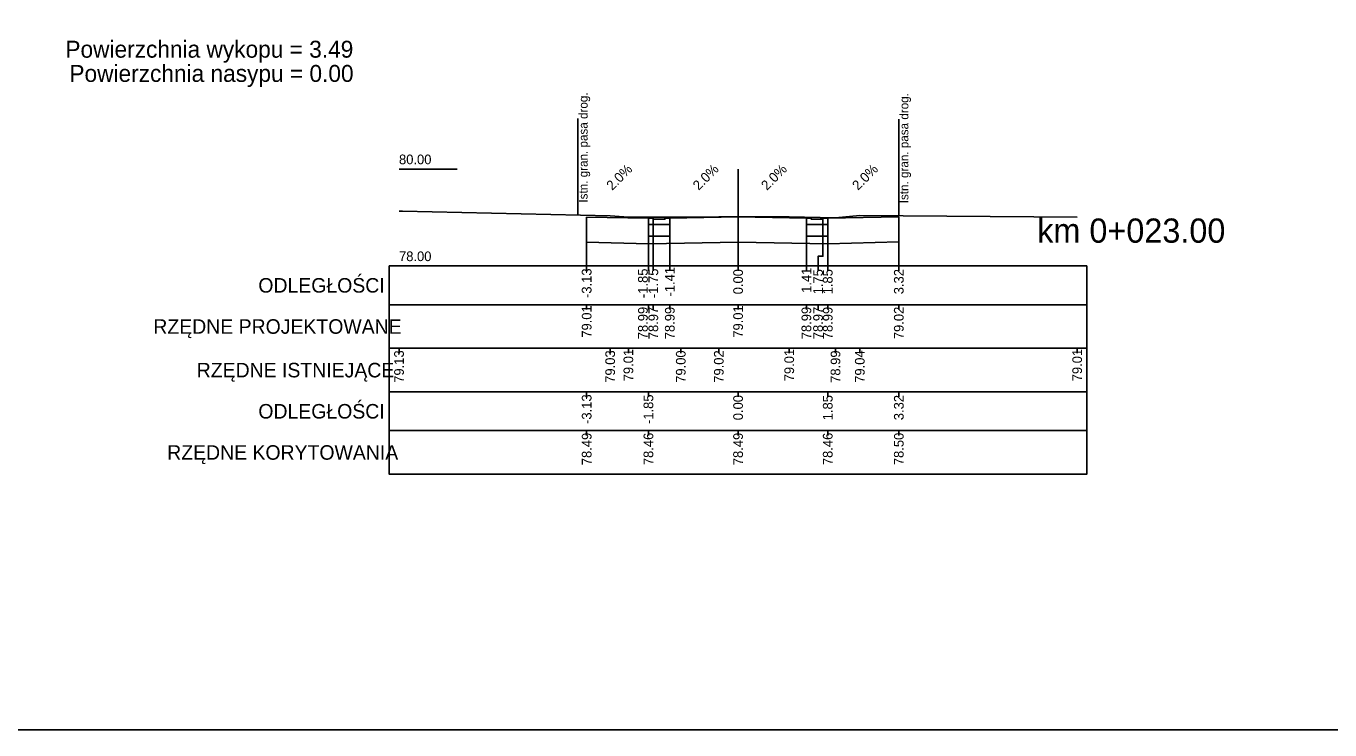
# Model space of a CAD drawing. Extents: x 7492871 to 7493499, y 5802964 to 5802992.
# Drawn here: x 7492987.07 to 7493013.99, y 5802963.88 to 5802978.41 of the extents above; entities that cross this region are included whole.
import ezdxf

# ---------------------------------------------------------------- set-up
doc = ezdxf.new("R2010")
doc.units = 0
for name, color, linetype in [('_wydruk', 7, 'Continuous'), ('d_pop_nasyp_opis', 7, 'Continuous'), ('d_pop_wykop_opis', 7, 'Continuous'), ('opisy_ramki_pop', 7, 'Continuous'), ('pop_comp_kostka', 7, 'Continuous'), ('pop_comp_lawa', 7, 'Continuous'), ('pop_comp_scieralna', 7, 'Continuous'), ('pop_granica_istn', 7, 'Continuous'), ('pop_opis', 7, 'Continuous'), ('pop_os', 7, 'Continuous'), ('pop_pikietaz', 7, 'Continuous'), ('pop_teren', 7, 'Continuous')]:
    doc.layers.add(name, color=color, linetype=linetype)

msp = doc.modelspace()

# ---------------------------------------------------------------- linework, layer by layer
msp.add_lwpolyline([(7492998.642, 5802974.47), (7492999.917, 5802974.445), (7493000.017, 5802974.445), (7493000.018, 5802974.425), (7493000.257, 5802974.425), (7493000.258, 5802974.445), (7493000.358, 5802974.445), (7493001.768, 5802974.473), (7493003.178, 5802974.445), (7493003.278, 5802974.445), (7493003.279, 5802974.425), (7493003.518, 5802974.425), (7493003.519, 5802974.445), (7493003.619, 5802974.445), (7493005.086, 5802974.474)])
at = {"layer": '_wydruk'}
msp.add_lwpolyline([(7492871.369, 5802992.281), (7493499.283, 5802992.281), (7493499.283, 5802963.881), (7492871.369, 5802963.881)], close=True, dxfattribs=at)
at = {"layer": 'opisy_ramki_pop'}
for points in [[(7492998.642, 5802973.95), (7492998.642, 5802973.659), (7492998.642, 5802973.659), (7492998.642, 5802973.459)], [(7492999.917, 5802973.916), (7492999.917, 5802973.659), (7492999.917, 5802973.659), (7492999.917, 5802973.459)], [(7493001.768, 5802973.953), (7493001.768, 5802973.659), (7493001.768, 5802973.659), (7493001.768, 5802973.459)], [(7493003.619, 5802973.916), (7493003.619, 5802973.659), (7493003.619, 5802973.659), (7493003.619, 5802973.459)], [(7493005.086, 5802973.954), (7493005.086, 5802973.659), (7493005.086, 5802973.659), (7493005.086, 5802973.459)]]:
    msp.add_lwpolyline(points, dxfattribs=at)
at = {"layer": 'pop_comp_kostka'}
for p, q in [((7493000.017, 5802974.445), (7492999.917, 5802974.445)), ((7492999.917, 5802974.445), (7492999.917, 5802974.315)), ((7492999.917, 5802974.315), (7493000.358, 5802974.315)), ((7493000.018, 5802974.425), (7493000.017, 5802974.445)), ((7493000.257, 5802974.425), (7493000.018, 5802974.425)), ((7493000.258, 5802974.445), (7493000.257, 5802974.425)), ((7493000.358, 5802974.445), (7493000.258, 5802974.445)), ((7493000.358, 5802974.315), (7493000.358, 5802974.445)), ((7493003.278, 5802974.445), (7493003.178, 5802974.445)), ((7493003.178, 5802974.445), (7493003.178, 5802974.315)), ((7493003.178, 5802974.315), (7493003.619, 5802974.315)), ((7493003.279, 5802974.425), (7493003.278, 5802974.445)), ((7493003.518, 5802974.425), (7493003.279, 5802974.425)), ((7493003.519, 5802974.445), (7493003.518, 5802974.425)), ((7493003.619, 5802974.445), (7493003.519, 5802974.445)), ((7493003.619, 5802974.315), (7493003.619, 5802974.445))]:
    msp.add_line(p, q, dxfattribs=at)
at = {"layer": 'pop_comp_lawa'}
for p, q in [((7493000.358, 5802974.315), (7492999.917, 5802974.315)), ((7492999.917, 5802974.315), (7492999.917, 5802974.075)), ((7493000.358, 5802974.075), (7493000.358, 5802974.315)), ((7493003.619, 5802974.315), (7493003.178, 5802974.315)), ((7493003.178, 5802974.315), (7493003.178, 5802974.075)), ((7493003.619, 5802974.075), (7493003.619, 5802974.315)), ((7492999.917, 5802974.075), (7493000.358, 5802974.075)), ((7493003.178, 5802974.075), (7493003.619, 5802974.075))]:
    msp.add_line(p, q, dxfattribs=at)
at = {"layer": 'pop_comp_scieralna'}
for p, q in [((7492999.917, 5802974.445), (7492998.642, 5802974.47)), ((7492998.642, 5802974.47), (7492998.642, 5802973.95)), ((7492999.917, 5802974.075), (7492999.917, 5802974.445)), ((7493001.768, 5802974.473), (7493000.358, 5802974.445)), ((7493000.358, 5802974.445), (7493000.358, 5802974.075)), ((7493001.768, 5802973.953), (7493001.768, 5802974.473)), ((7493003.178, 5802974.445), (7493001.768, 5802974.473)), ((7493001.768, 5802974.473), (7493001.768, 5802973.953)), ((7493003.178, 5802974.075), (7493003.178, 5802974.445)), ((7493005.086, 5802974.474), (7493003.619, 5802974.445)), ((7493003.619, 5802974.445), (7493003.619, 5802974.075)), ((7493005.086, 5802973.954), (7493005.086, 5802974.474)), ((7493000.358, 5802974.075), (7492999.917, 5802974.075)), ((7493003.619, 5802974.075), (7493003.178, 5802974.075)), ((7492998.642, 5802973.95), (7492999.917, 5802973.916)), ((7492999.917, 5802973.916), (7493001.768, 5802973.953)), ((7493001.768, 5802973.953), (7493003.619, 5802973.916)), ((7493003.619, 5802973.916), (7493005.086, 5802973.954))]:
    msp.add_line(p, q, dxfattribs=at)
at = {"layer": 'pop_granica_istn'}
for p, q in [((7492998.463, 5802975.006), (7492998.463, 5802976.506)), ((7493005.086, 5802974.992), (7493005.086, 5802976.492)), ((7492998.463, 5802974.506), (7492998.463, 5802975.006)), ((7493005.086, 5802974.492), (7493005.086, 5802974.992))]:
    msp.add_line(p, q, dxfattribs=at)
at = {"layer": 'pop_opis'}
for p, q in [((7492994.768, 5802975.459), (7492995.968, 5802975.459)), ((7492994.568, 5802973.459), (7492994.568, 5802971.759)), ((7492994.568, 5802973.459), (7492994.568, 5802971.759)), ((7492994.568, 5802973.459), (7492994.568, 5802971.759)), ((7492994.568, 5802973.459), (7492994.568, 5802971.759)), ((7492994.768, 5802973.459), (7492995.968, 5802973.459)), ((7492998.642, 5802973.359), (7492998.642, 5802973.459)), ((7492999.917, 5802973.359), (7492999.917, 5802973.459)), ((7493000.018, 5802973.359), (7493000.018, 5802973.459)), ((7493000.358, 5802973.359), (7493000.358, 5802973.459)), ((7493001.768, 5802973.359), (7493001.768, 5802973.459)), ((7493003.178, 5802973.359), (7493003.178, 5802973.459)), ((7493003.419, 5802973.359), (7493003.419, 5802973.459)), ((7493003.619, 5802973.359), (7493003.619, 5802973.459)), ((7493005.086, 5802973.359), (7493005.086, 5802973.459)), ((7492994.568, 5802972.659), (7493008.968, 5802972.659)), ((7492994.568, 5802972.659), (7493008.968, 5802972.659)), ((7492994.568, 5802972.659), (7493008.968, 5802972.659)), ((7492994.568, 5802972.659), (7493008.968, 5802972.659)), ((7492998.642, 5802972.559), (7492998.642, 5802972.659)), ((7492999.917, 5802972.559), (7492999.917, 5802972.659)), ((7493000.018, 5802972.559), (7493000.018, 5802972.659)), ((7493000.358, 5802972.559), (7493000.358, 5802972.659)), ((7493001.768, 5802972.559), (7493001.768, 5802972.659)), ((7493003.178, 5802972.559), (7493003.178, 5802972.659)), ((7493003.419, 5802972.559), (7493003.419, 5802972.659)), ((7493003.619, 5802972.559), (7493003.619, 5802972.659)), ((7493005.086, 5802972.559), (7493005.086, 5802972.659)), ((7492994.568, 5802971.759), (7492994.568, 5802970.859)), ((7492994.768, 5802971.659), (7492994.768, 5802971.759)), ((7492999.127, 5802971.659), (7492999.127, 5802971.759)), ((7492999.503, 5802971.659), (7492999.503, 5802971.759)), ((7493000.585, 5802971.659), (7493000.585, 5802971.759)), ((7493001.37, 5802971.659), (7493001.37, 5802971.759)), ((7493002.824, 5802971.659), (7493002.824, 5802971.759)), ((7493003.779, 5802971.659), (7493003.779, 5802971.759)), ((7493004.281, 5802971.659), (7493004.281, 5802971.759)), ((7493008.768, 5802971.659), (7493008.768, 5802971.759)), ((7492994.568, 5802970.859), (7492994.568, 5802969.159)), ((7492998.642, 5802970.759), (7492998.642, 5802970.859)), ((7492999.917, 5802970.759), (7492999.917, 5802970.859)), ((7493001.768, 5802970.759), (7493001.768, 5802970.859)), ((7493003.619, 5802970.759), (7493003.619, 5802970.859)), ((7493005.086, 5802970.759), (7493005.086, 5802970.859)), ((7492994.568, 5802970.059), (7493008.968, 5802970.059)), ((7492998.642, 5802969.959), (7492998.642, 5802970.059)), ((7492999.917, 5802969.959), (7492999.917, 5802970.059)), ((7493001.768, 5802969.959), (7493001.768, 5802970.059)), ((7493003.619, 5802969.959), (7493003.619, 5802970.059)), ((7493005.086, 5802969.959), (7493005.086, 5802970.059))]:
    msp.add_line(p, q, dxfattribs=at)
for points in [[(7492998.642, 5802974.47), (7492998.642, 5802973.659), (7492998.642, 5802973.659), (7492998.642, 5802973.459)], [(7492999.917, 5802974.445), (7492999.917, 5802973.659), (7492999.917, 5802973.659), (7492999.917, 5802973.459)], [(7493000.018, 5802974.425), (7493000.018, 5802973.659), (7493000.018, 5802973.659), (7493000.018, 5802973.459)], [(7493000.358, 5802974.445), (7493000.358, 5802973.659), (7493000.358, 5802973.659), (7493000.358, 5802973.459)], [(7493001.768, 5802974.473), (7493001.768, 5802973.659), (7493001.768, 5802973.659), (7493001.768, 5802973.459)], [(7493003.178, 5802974.445), (7493003.178, 5802973.659), (7493003.178, 5802973.659), (7493003.178, 5802973.459)], [(7493003.518, 5802974.425), (7493003.518, 5802973.659), (7493003.419, 5802973.659), (7493003.419, 5802973.459)], [(7493003.619, 5802974.445), (7493003.619, 5802973.659), (7493003.619, 5802973.659), (7493003.619, 5802973.459)], [(7493005.086, 5802974.474), (7493005.086, 5802973.659), (7493005.086, 5802973.659), (7493005.086, 5802973.459)]]:
    msp.add_lwpolyline(points, dxfattribs=at)
for points in [[(7492994.568, 5802973.459), (7492994.568, 5802971.759), (7493008.968, 5802971.759), (7493008.968, 5802973.459)], [(7492994.568, 5802973.459), (7492994.568, 5802971.759), (7493008.968, 5802971.759), (7493008.968, 5802973.459)], [(7492994.568, 5802973.459), (7492994.568, 5802971.759), (7493008.968, 5802971.759), (7493008.968, 5802973.459)], [(7492994.568, 5802973.459), (7492994.568, 5802971.759), (7493008.968, 5802971.759), (7493008.968, 5802973.459)], [(7492994.568, 5802971.759), (7492994.568, 5802970.859), (7493008.968, 5802970.859), (7493008.968, 5802971.759)], [(7492994.568, 5802970.859), (7492994.568, 5802969.159), (7493008.968, 5802969.159), (7493008.968, 5802970.859)]]:
    msp.add_lwpolyline(points, close=True, dxfattribs=at)
at = {"layer": 'pop_os'}
msp.add_line((7493001.768, 5802975.459), (7493001.768, 5802973.459), dxfattribs=at)
at = {"layer": 'pop_teren'}
msp.add_lwpolyline([(7492994.768, 5802974.592), (7492994.839, 5802974.592), (7492999.127, 5802974.491), (7492999.503, 5802974.47), (7493000.585, 5802974.464), (7493001.37, 5802974.474), (7493002.824, 5802974.472), (7493003.779, 5802974.453), (7493004.281, 5802974.498), (7493008.768, 5802974.467)], dxfattribs=at)

# ---------------------------------------------------------------- texts
at = {"layer": 'd_pop_nasyp_opis'}
msp.add_text('Powierzchnia nasypu = 0.00', height=0.35, dxfattribs=at).set_placement((7492987.963, 5802977.259))
at = {"layer": 'd_pop_wykop_opis'}
msp.add_text('Powierzchnia wykopu = 3.49', height=0.35, dxfattribs=at).set_placement((7492987.88, 5802977.759))
at = {"layer": 'pop_granica_istn'}
for p in [(7492998.661, 5802974.767), (7493005.284, 5802974.753)]:
    msp.add_text('Istn. gran. pasa drog.', height=0.18, rotation=90, dxfattribs=at).set_placement(p)
at = {"layer": 'pop_opis'}
for s, height, p in [('80.00', 0.2, (7492994.768, 5802975.559)), ('78.00', 0.2, (7492994.768, 5802973.559)), ('ODLEGŁOŚCI', 0.3, (7492991.864, 5802972.909)), ('ODLEGŁOŚCI', 0.3, (7492991.864, 5802972.909)), ('ODLEGŁOŚCI', 0.3, (7492991.864, 5802972.909)), ('ODLEGŁOŚCI', 0.3, (7492991.864, 5802972.909)), ('RZĘDNE PROJEKTOWANE', 0.3, (7492989.696, 5802972.059)), ('RZĘDNE PROJEKTOWANE', 0.3, (7492989.696, 5802972.059)), ('RZĘDNE PROJEKTOWANE', 0.3, (7492989.696, 5802972.059)), ('RZĘDNE PROJEKTOWANE', 0.3, (7492989.696, 5802972.059)), ('RZĘDNE ISTNIEJĄCE', 0.3, (7492990.592, 5802971.159)), ('ODLEGŁOŚCI', 0.3, (7492991.864, 5802970.309)), ('RZĘDNE KORYTOWANIA', 0.3, (7492989.982, 5802969.459))]:
    msp.add_text(s, height=height, dxfattribs=at).set_placement(p)
for s, rotation, p in [('2.0%', 45, (7492999.17, 5802975.008)), ('2.0%', 45, (7493000.954, 5802975.009)), ('2.0%', 45, (7493002.364, 5802975.009)), ('2.0%', 45, (7493004.244, 5802975.009)), ('-3.13', 90, (7492998.742, 5802972.798)), ('-1.85', 90, (7492999.903, 5802972.796)), ('-1.75', 90, (7493000.118, 5802972.796)), ('-1.41', 90, (7493000.458, 5802972.829)), ('0.00', 90, (7493001.868, 5802972.874)), ('1.41', 90, (7493003.278, 5802972.905)), ('1.75', 90, (7493003.519, 5802972.873)), ('1.85', 90, (7493003.719, 5802972.873)), ('3.32', 90, (7493005.186, 5802972.875)), ('79.01', 90, (7492998.742, 5802971.978)), ('78.99', 90, (7492999.903, 5802971.946)), ('78.97', 90, (7493000.118, 5802971.947)), ('78.99', 90, (7493000.458, 5802971.946)), ('79.01', 90, (7493001.868, 5802971.978)), ('78.99', 90, (7493003.278, 5802971.946)), ('78.97', 90, (7493003.519, 5802971.947)), ('78.99', 90, (7493003.719, 5802971.946)), ('79.02', 90, (7493005.186, 5802971.948)), ('79.13', 90, (7492994.868, 5802971.047)), ('79.03', 90, (7492999.227, 5802971.047)), ('79.01', 90, (7492999.603, 5802971.078)), ('79.00', 90, (7493000.685, 5802971.047)), ('79.02', 90, (7493001.47, 5802971.048)), ('79.01', 90, (7493002.924, 5802971.078)), ('78.99', 90, (7493003.879, 5802971.046)), ('79.04', 90, (7493004.381, 5802971.047)), ('79.01', 90, (7493008.868, 5802971.078)), ('-3.13', 90, (7492998.742, 5802970.198)), ('-1.85', 90, (7493000.017, 5802970.196)), ('0.00', 90, (7493001.868, 5802970.274)), ('1.85', 90, (7493003.719, 5802970.273)), ('3.32', 90, (7493005.186, 5802970.275)), ('78.49', 90, (7492998.742, 5802969.346)), ('78.46', 90, (7493000.017, 5802969.347)), ('78.49', 90, (7493001.868, 5802969.346)), ('78.46', 90, (7493003.719, 5802969.347)), ('78.50', 90, (7493005.186, 5802969.347))]:
    msp.add_text(s, height=0.2, rotation=rotation, dxfattribs=at).set_placement(p)
at = {"layer": 'pop_pikietaz'}
msp.add_text('km 0+023.00', height=0.5, dxfattribs=at).set_placement((7493007.944, 5802973.939))

doc.saveas('drawing.dxf')
